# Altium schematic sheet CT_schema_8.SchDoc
size 374 x 335 mm
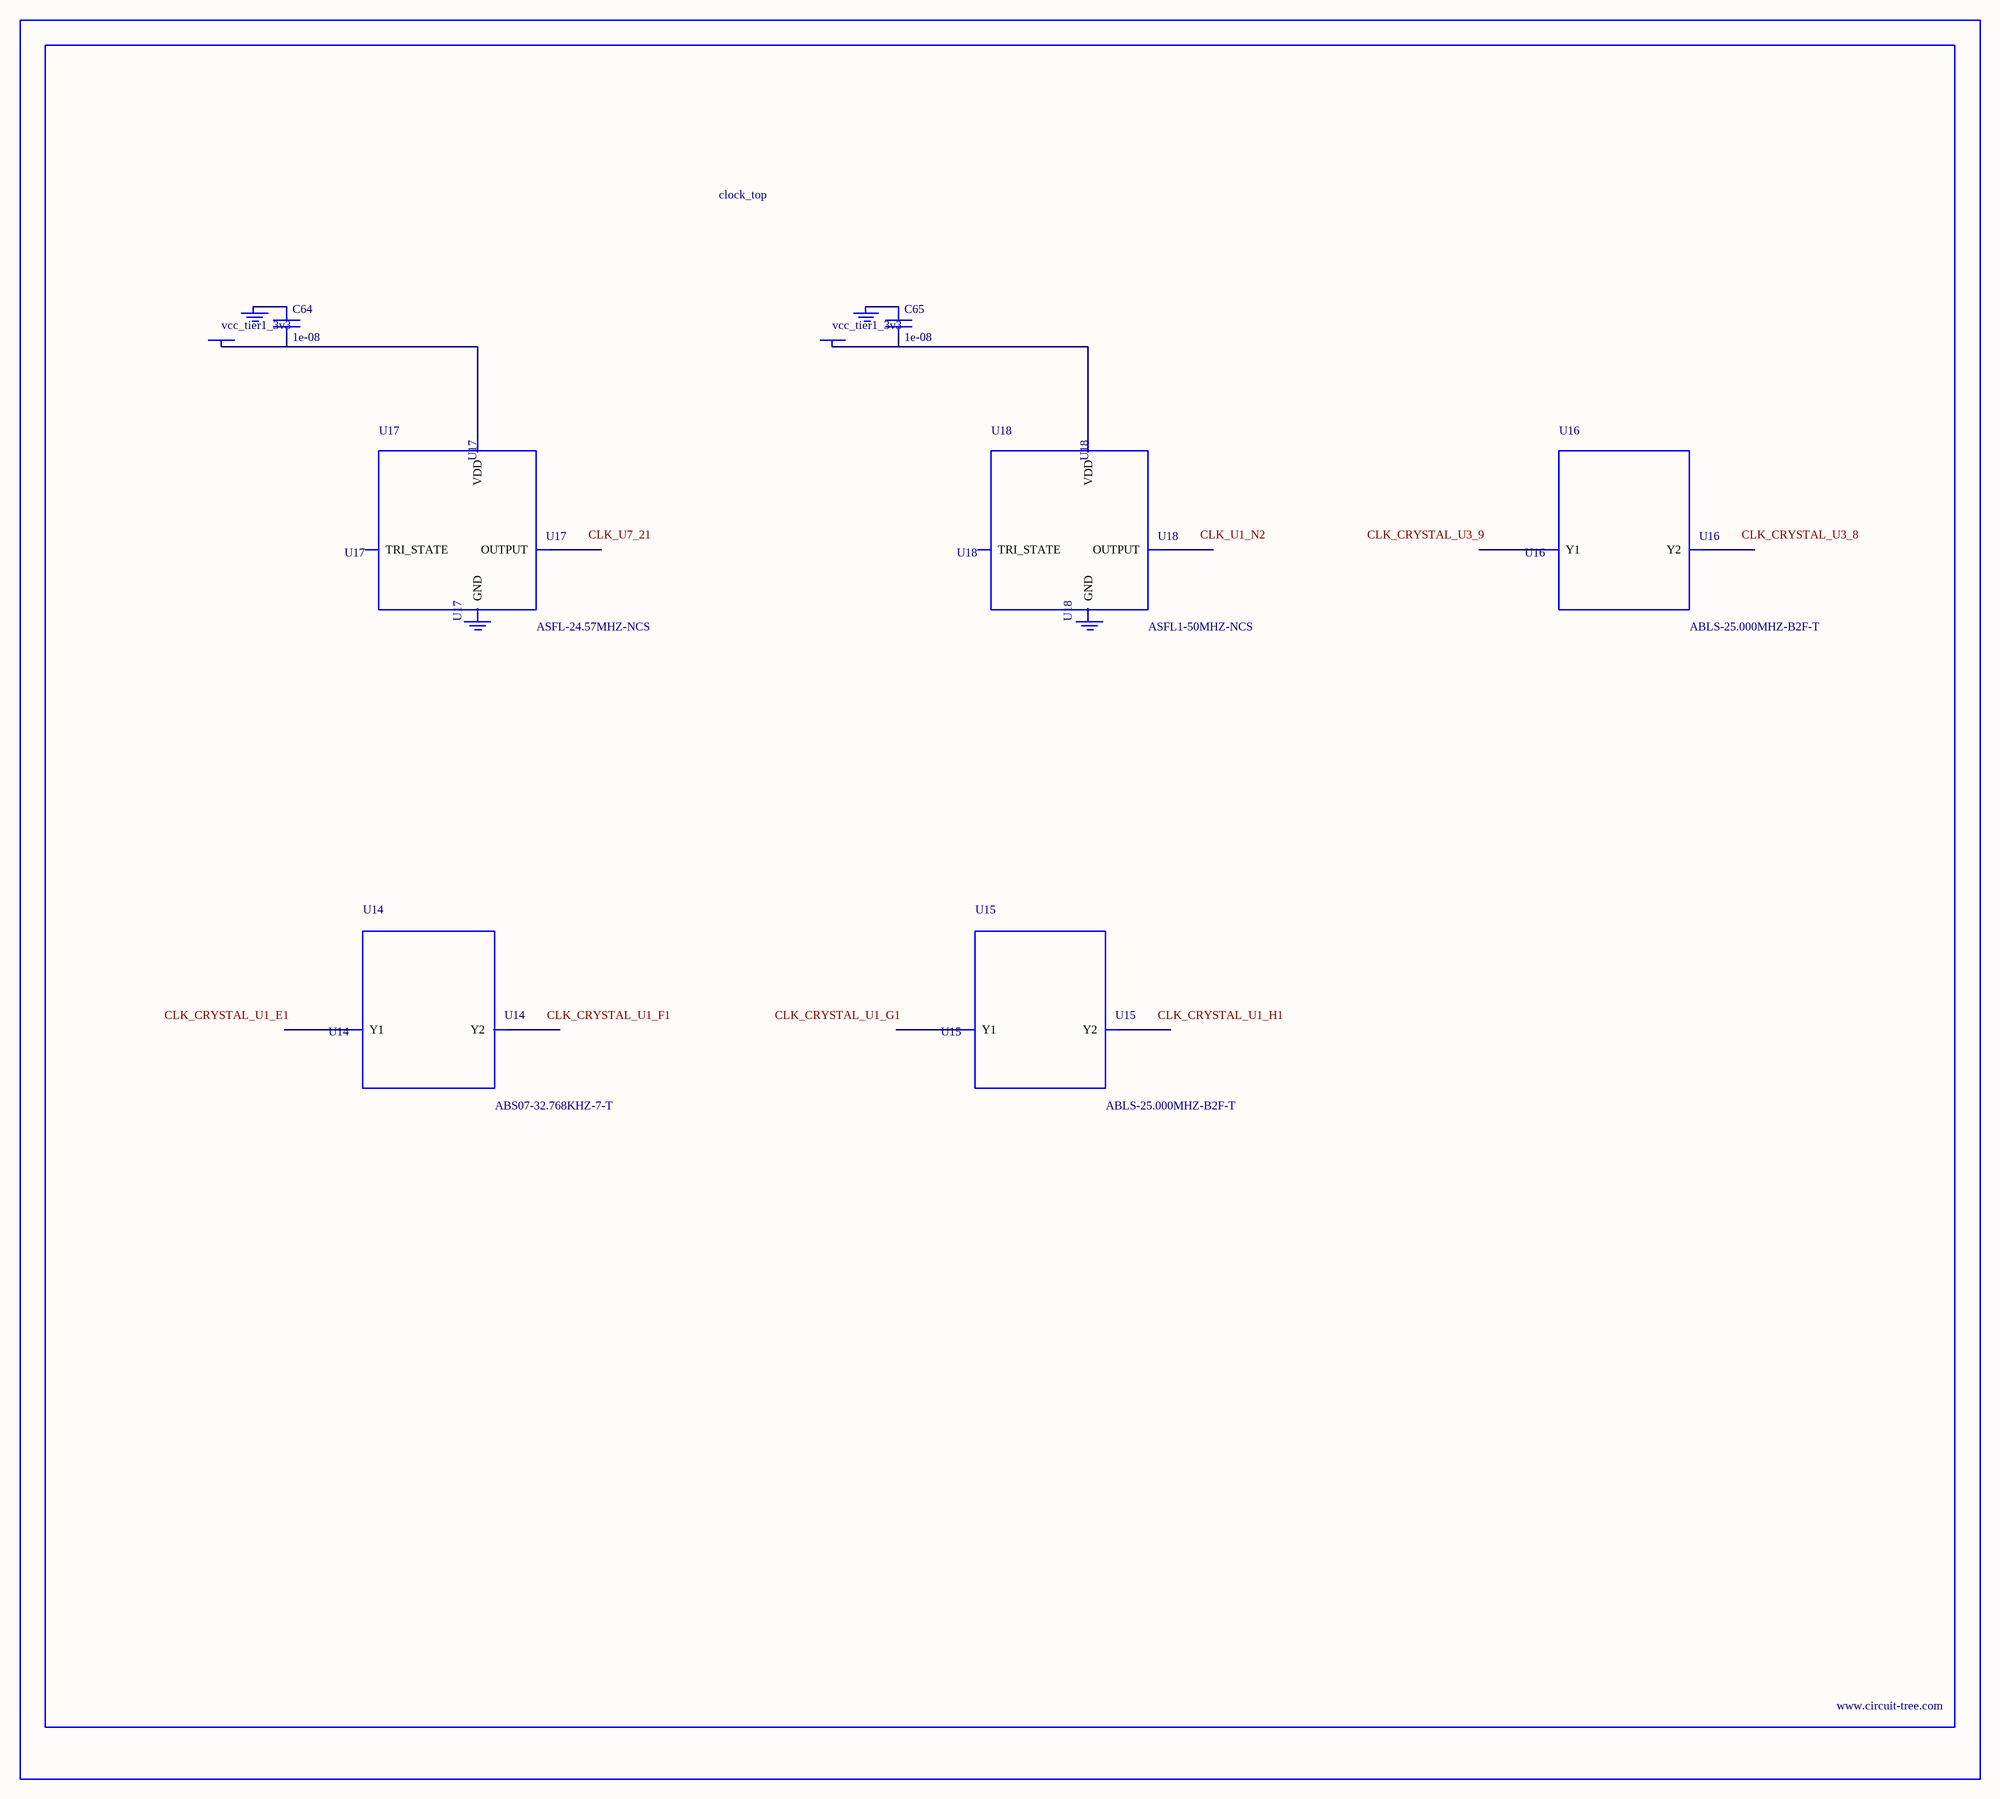
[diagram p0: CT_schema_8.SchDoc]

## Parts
BORDER7  (no value)
C64  1e-08  [C0402]
C65  1e-08  [C0402]
GND_INSTANCE_7_0  (no value)
GND_INSTANCE_7_1  (no value)
GND_INSTANCE_7_2  (no value)
GND_INSTANCE_7_3  (no value)
POWER_INSTANCE_7_0  vcc_tier1_3v3
POWER_INSTANCE_7_1  vcc_tier1_3v3
U14  ABS07-32.768KHZ-7-T  [ABS07-32.768KHZ-7-T]
U15  ABLS-25.000MHZ-B2F-T  [ABLS-25.000MHZ-B2F-T]
U16  ABLS-25.000MHZ-B2F-T  [ABLS-25.000MHZ-B2F-T]
U17  ASFL-24.57MHZ-NCS  [ASFL1]
U18  ASFL1-50MHZ-NCS  [ASFL1]

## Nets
NetC64_1: C64.1 GND_INSTANCE_7_0.0(GND)
NetC64_2: C64.2 POWER_INSTANCE_7_0.0(PWR) U17.4(VDD)
NetC65_1: C65.1 GND_INSTANCE_7_2.0(GND)
NetC65_2: C65.2 POWER_INSTANCE_7_1.0(PWR) U18.4(VDD)

Not connected (* = marked no-connect by the designer): GND_INSTANCE_7_1 0(GND); GND_INSTANCE_7_3 0(GND); U14 1(Y1) 2(Y2); U15 1(Y1) 2(Y2); U16 1(Y1) 2(Y2); U17 1(TRI_STATE) 2(GND) 3(OUTPUT); U18 1(TRI_STATE) 2(GND) 3(OUTPUT)

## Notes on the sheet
- Labels drawn without touching a wire or pin: CLK_CRYSTAL_U1_E1, CLK_CRYSTAL_U1_F1, CLK_CRYSTAL_U1_G1, CLK_CRYSTAL_U1_H1, CLK_CRYSTAL_U3_8, CLK_CRYSTAL_U3_9, CLK_U1_N2, CLK_U7_21

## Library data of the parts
BORDER7 = BORDER_PAGE7
C64 C65 = C0402C103K3RAC
GND_INSTANCE_7_0-GND_INSTANCE_7_3 = GND
POWER_INSTANCE_7_0 POWER_INSTANCE_7_1 = PWR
